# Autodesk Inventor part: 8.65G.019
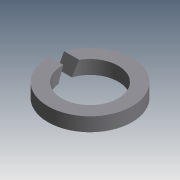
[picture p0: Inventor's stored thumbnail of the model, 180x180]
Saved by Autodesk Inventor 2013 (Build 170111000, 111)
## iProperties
Shininess: 25.0
Length Units: 11269
Angle Units: 11279
Time Units: 11290
Mass Units: 11283
Length Display Precision: 3
Angle Display Precision: 2
Created: 2001-04
Material: Steel, Mild
Document SubType Name: Modeling
Designer: tevgeniy
Density: 7.86 g/cm^3
Density: 0.0
Volumn: 0.0
Area: 0.0
PropertySet Name: Model Information
Control State: 0
Master: False
Checked Out: False
Last Check In Date: 2008-10-15
Checked Out Date: 2008-10-15
Author: tevgeniy
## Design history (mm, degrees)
node "ExtrusionBlind1" dims "d2" = 2, "d3" = 0
  sketch "Sketch1"
    geometry: C1 r 6.1 at (-266.435, -313.047)
    constraints: 1 centre point, 1 other
    dimensions: "d1" = 12.2 diameter of C1
node "Hole1" dims "d5" = 8.2, "d6" = 4, "d7" = 2, "d8" = 60 deg, "d9" = 8, "d10" = 118 deg
  sketch "Sketch2"
    geometry: C1 r 6.1 at (0, 0) reference
node "WorkAxis1"
workplane "Work Plane1"
workplane "Work Plane2"
node "WorkPlane1"
node "ExtrusionToFace1" dims "d18" = 0.13, "d19" = 0
  sketch "Sketch3"
    geometry: L1 (-17.369, -0.228)-(-17.369, -2); L2 (-15.369, 0.5)-(-17.369, -0.228); L3 (-15.369, -1.272)-(-15.369, 0.5); L4 (-17.369, -2)-(-15.369, -1.272); L5 (-7.684, 0)-(-25.053, 0); C1 r 6.1 at (-15.369, 0); C2 r 6.1 at (-17.369, 0)
    constraints: 10 end point, 2 centre point, 2 parallel, 1 vertical
    dimensions: "d13" = 0 horizontal distance of L2.start C1.centre; "d15" = 0 horizontal distance of L1.start C2.centre; "d17" = 160 deg angle of L4 L5
body "Solid1"
other parameters: "d0" = 12.2 (derived), "d4" = 0, "d11" = 0, "d12" = 0 (derived), "d14" = 0 (derived), "d16" = 160 deg (derived)
